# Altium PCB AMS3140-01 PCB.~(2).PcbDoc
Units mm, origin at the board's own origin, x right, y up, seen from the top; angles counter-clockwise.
Board outline 41 x 38 mm, 4 copper layers (Top Layer, Int1_T, Int2-B, Bottom (GND)), stack 1.57 mm thick; 5 components, 68 nets, 22 pads, 0 vias.
Unrouted connection lines stored in the file: 5.
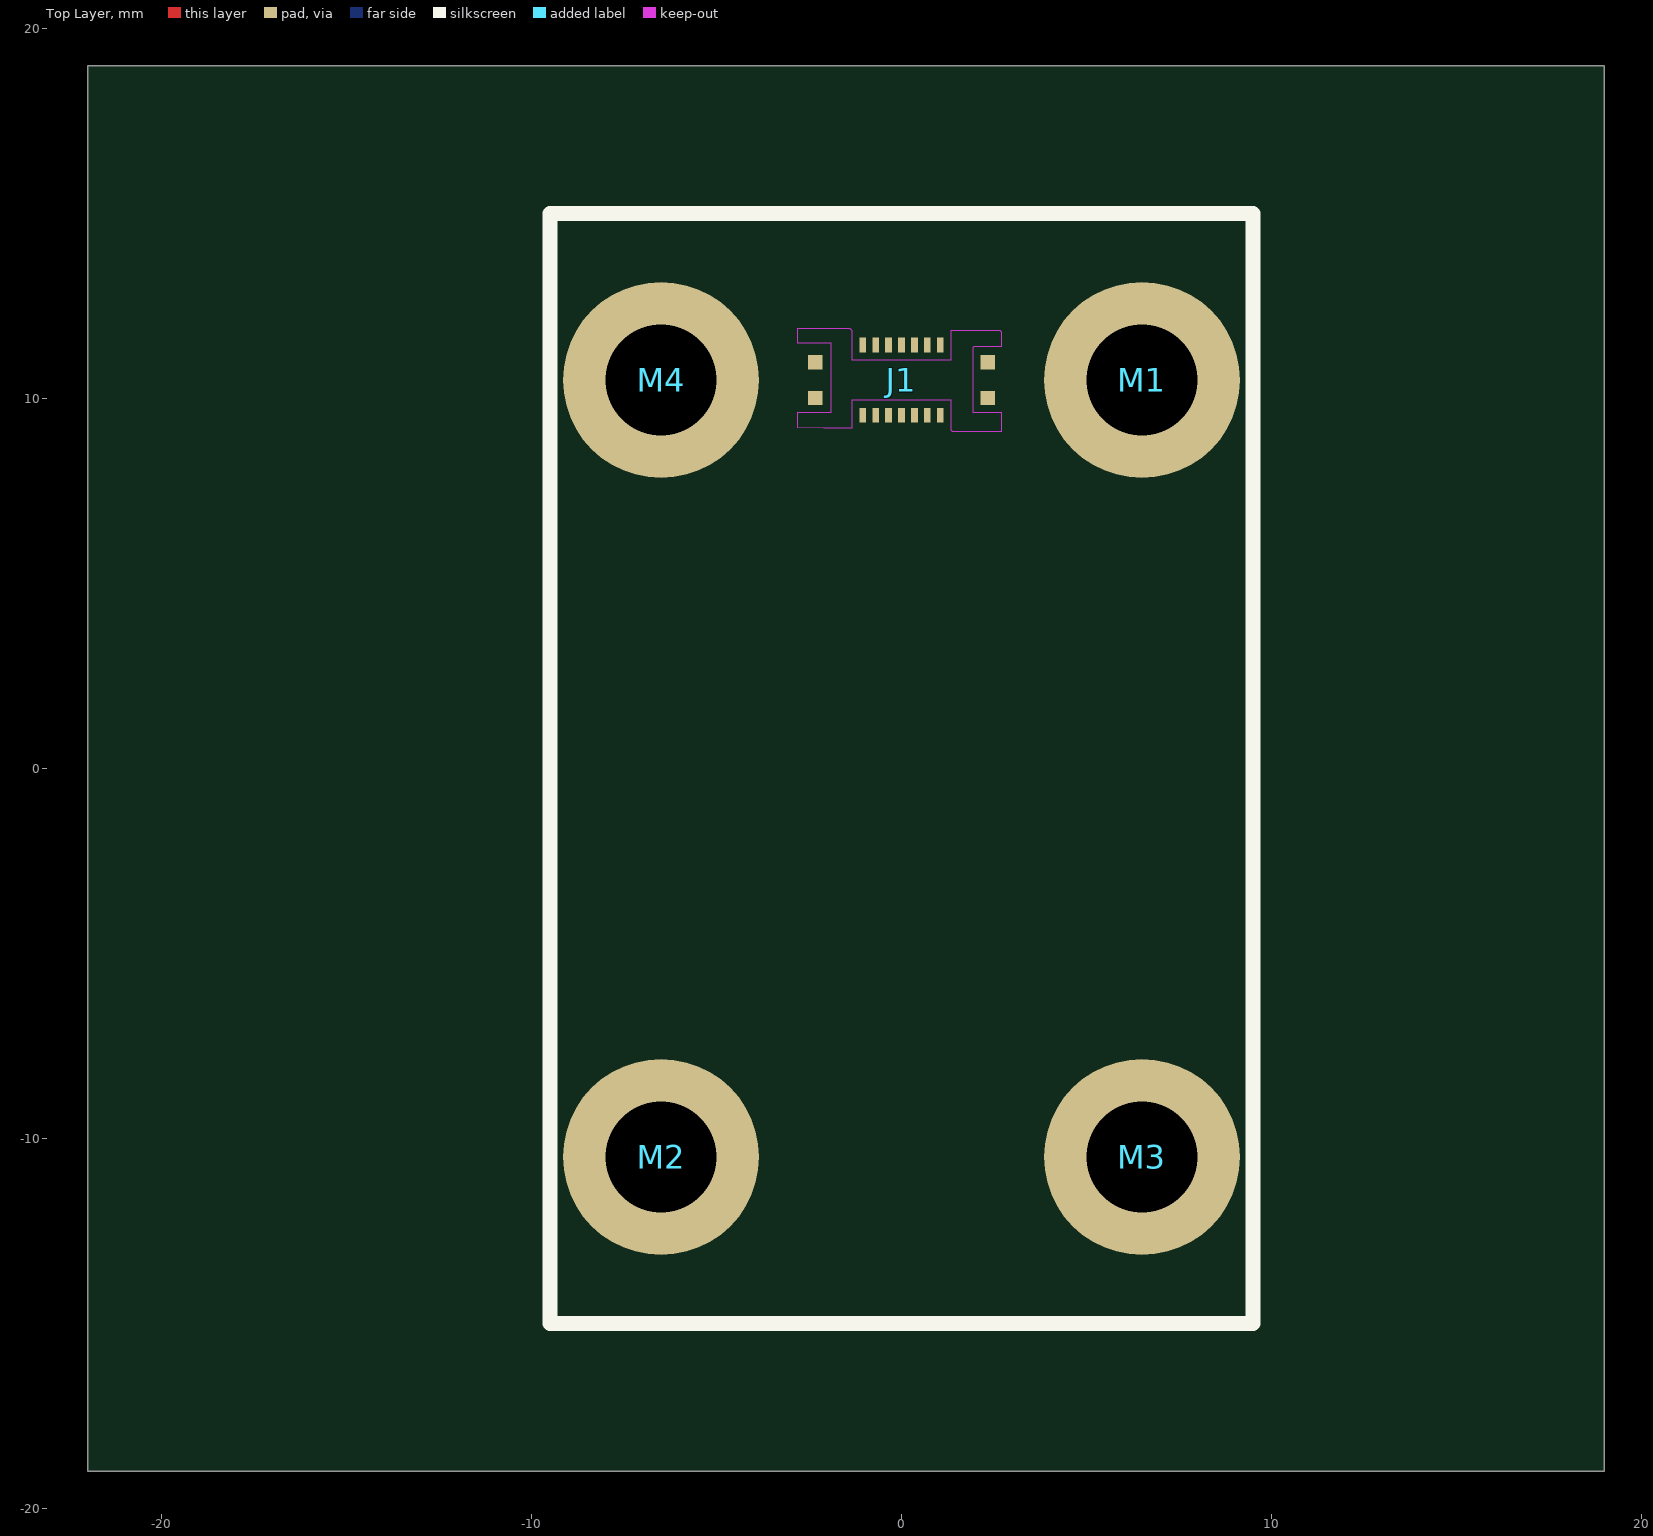
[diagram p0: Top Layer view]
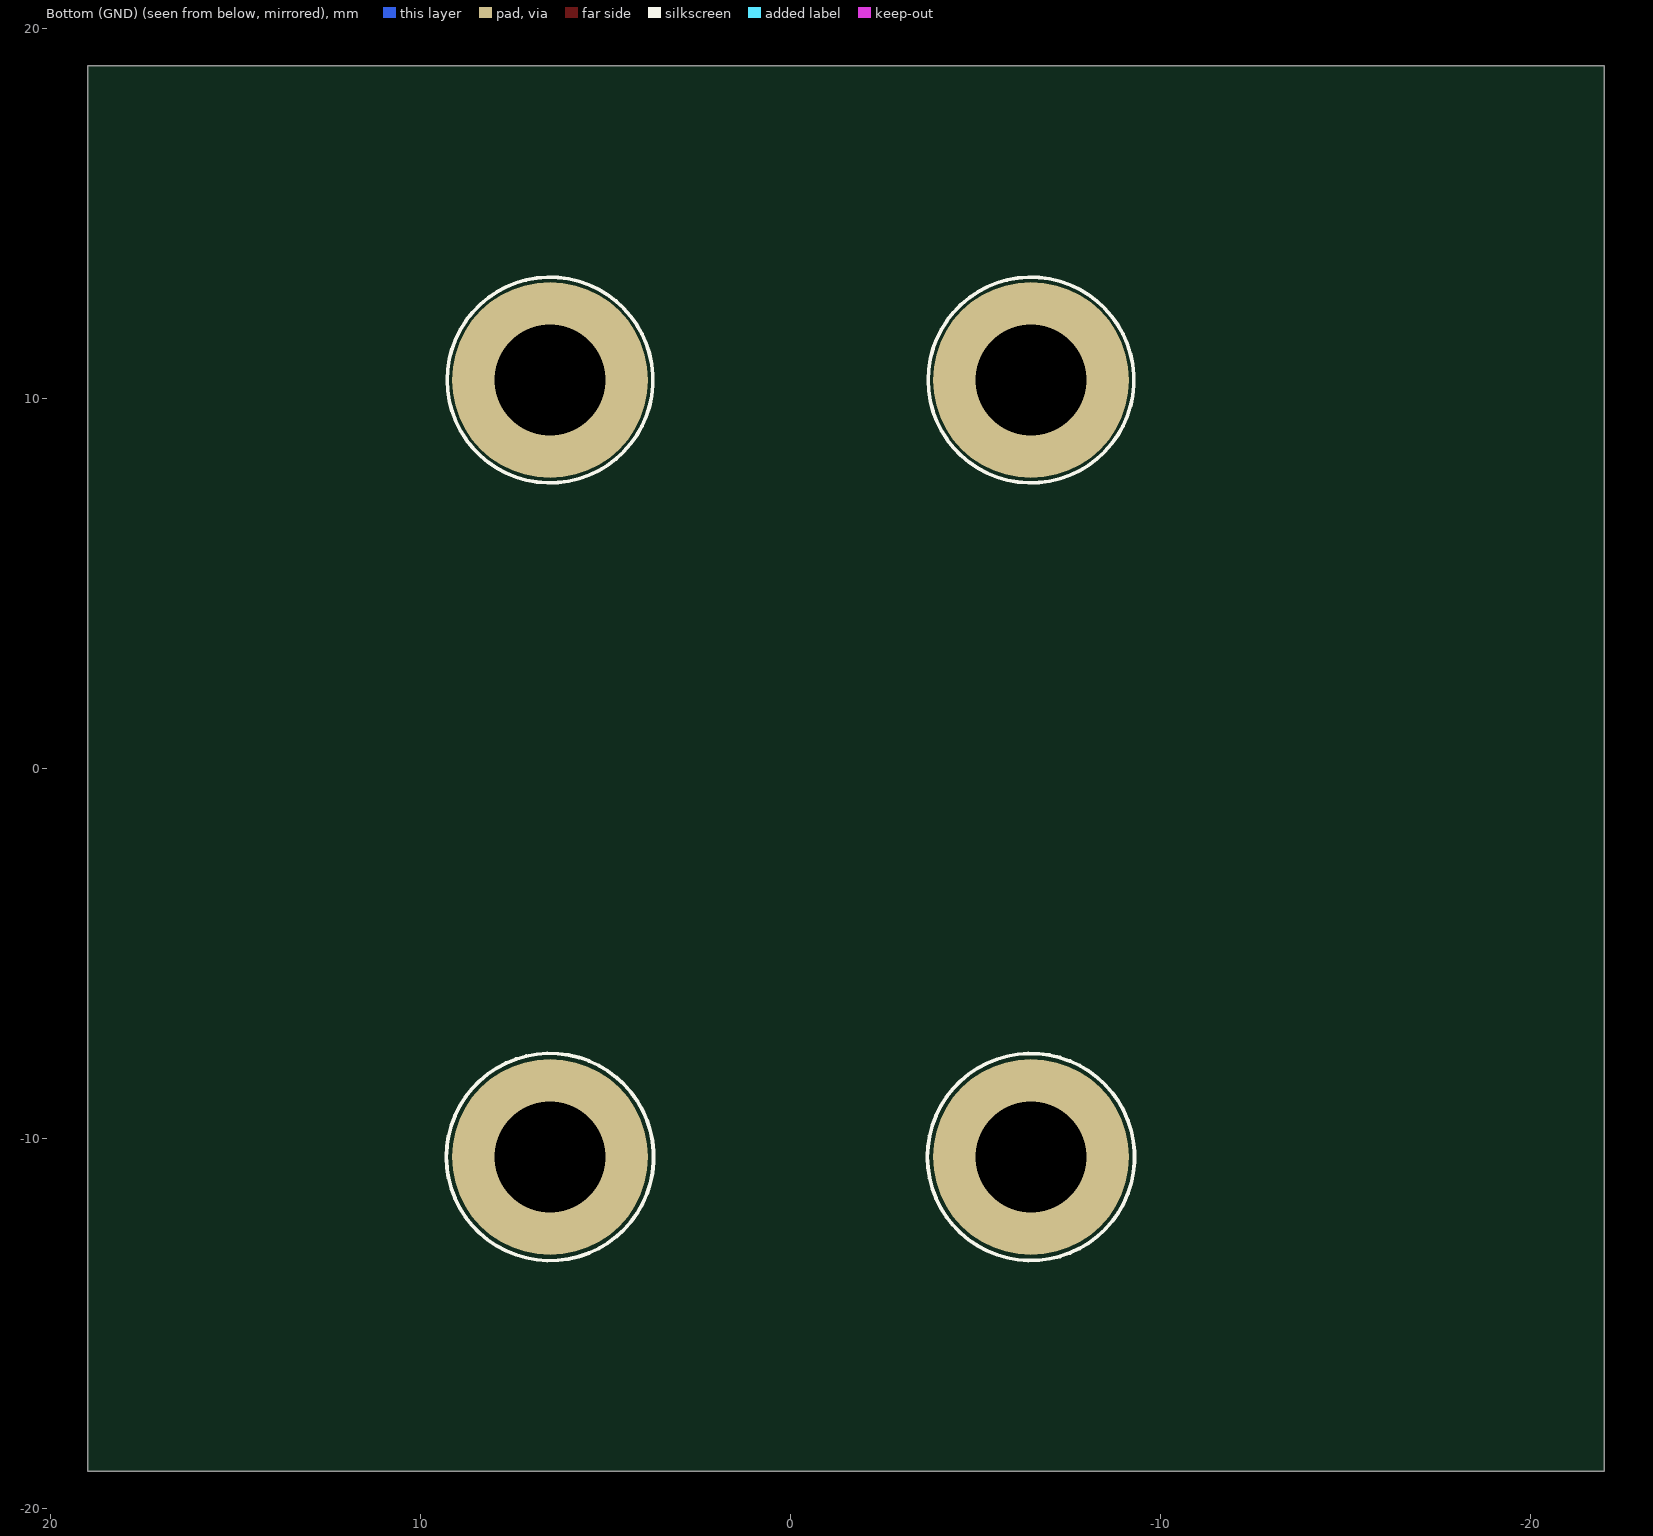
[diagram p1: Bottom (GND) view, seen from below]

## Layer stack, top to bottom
Top Solder: solder mask 0.025, SM-001, Dk 4
Top Layer: signal copper 0.035
Dielectric 1: core 0.36, Core-009, Dk 4.5
Int1_T: signal copper 0.035
Dielectric 6: prepreg 0.71, PP-006, Dk 4.1
Int2-B: signal copper 0.035
Dielectric 11: core 0.36, Core-009, Dk 4.5
Bottom (GND): signal copper 0.035
Bottom Solder: solder mask 0.025, SM-001, Dk 4

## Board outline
-22,-19 -22,19 19,19 19,-19

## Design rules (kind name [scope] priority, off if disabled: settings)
BoardOutlineClearance "BoardOutlineClearance inner layers" [(not IsKeepOut) and onMid] p1: gap=0.4 ignorepadtopadclearanceinfootprint=FALSE
BoardOutlineClearance "BoardOutlineClearance_1 outer layers" [(not IsKeepOut) and OnOutside] p2: gap=0.25 ignorepadtopadclearanceinfootprint=FALSE
Clearance Clearance_poly_50Ohm [InNetClass('50ohm')] p1: gap=0.3 ignorepadtopadclearanceinfootprint=FALSE except(0: Arc-Hole Track-Hole SMDPad-Hole THPad-Hole Via-Hole Fill-Hole Poly-Hole Region-Hole Text-Hole)
Clearance [not IsKeepOut vs not IsKeepOut] p2: gap=0.15 ignorepadtopadclearanceinfootprint=FALSE except(0: Arc-Hole Track-Hole SMDPad-Hole THPad-Hole Via-Hole Fill-Hole Poly-Hole Region-Hole Text-Hole; 0.2: Arc-Poly Track-Poly SMDPad-Poly THPad-Poly Via-Poly Fill-Poly Poly-Poly)
Clearance Clearance_keepout [All] p3: gap=0.001 ignorepadtopadclearanceinfootprint=FALSE except(0: Arc-Hole Track-Hole SMDPad-Hole THPad-Hole Via-Hole Fill-Hole Poly-Hole Region-Hole Text-Hole)
ComponentClearance [All] p1: gap=0.25 collisioncheckmode=3 verticalgap=0.2 showdistances=FALSE
DiffPairsRouting [All] p1: maxlimit=0.15 minlimit=0.15 mostfreqgap=0.15 toplayer_minwidth=0.15 toplayer_maxwidth=0.7 toplayer_prefwidth=0.15 midlayer1_minwidth=0.15 midlayer1_maxwidth=0.7 midlayer1_prefwidth=0.15 midlayer4_minwidth=0.15 midlayer4_maxwidth=0.7 midlayer4_prefwidth=0.15 bottomlayer_minwidth=0.15 bottomlayer_maxwidth=0.7 bottomlayer_prefwidth=0.15 maxuncoupledlength=12.5
Height [All] p1: minheight=0 maxheight=25 prefheight=12.5
HoleSize HoleSize-PTH [All] p1: absolutevalues=TRUE maxlimit=4 minlimit=0.25 maxpercent=80.000 minpercent=20.000
HoleToHoleClearance [All] p1: gap=0.35 allowstackedmicrovias=TRUE
MatchedLengths "Schematic Matched Net Lengths_1" [InNet('OUT_P')] p1: tolerance=2 checknetsindiffpair=TRUE checkdiffpairvsdiffpair=FALSE checkxsignals=FALSE checkothers=FALSE
MatchedLengths "Schematic Matched Net Lengths" [InNet('OUT_N')] p2: tolerance=2 checknetsindiffpair=TRUE checkdiffpairvsdiffpair=FALSE checkxsignals=FALSE checkothers=FALSE
MaxMinImpedance "Schematic Impedance Constraint_7" [InNet('OUTF_P')] p1: minimum=47,00 maximum=53,00
MaxMinImpedance "Schematic Impedance Constraint_6" [InNet('OUTF_N')] p2: minimum=47,00 maximum=53,00
MaxMinImpedance "Schematic Impedance Constraint_3" [InNet('NetR12_2')] p3: minimum=47,00 maximum=53,00
MaxMinImpedance "Schematic Impedance Constraint_2" [InNet('NetJ3_1')] p4: minimum=47,00 maximum=53,00
MinimumAnnularRing AR [All] p1: minimumring=0.174
MinimumSolderMaskSliver [All] p1: minsoldermaskwidth=0.08
PlaneClearance PlaneClearance-IPI [All] p1: clearance=0.25
PolygonConnect PolygonConnect-via [IsVia] p1: connectstyle=Direct reliefconductorwidth=0.254 reliefentries=4 polygonreliefangle="45 Angle" airgapwidth=0.254
PolygonConnect PolygonConnect-xTW_1_bottom [All vs OnLayer('Bottom Layer')] p2: connectstyle=Direct reliefconductorwidth=0.254 reliefentries=4 polygonreliefangle="90 Angle" airgapwidth=0.254
PolygonConnect PolygonConnect-xTW_1_bottom_1 [(PadIsPlated = 'False')] p3: connectstyle=Relief reliefconductorwidth=0.2 reliefentries=4 polygonreliefangle="90 Angle" airgapwidth=0.2
PolygonConnect PolygonConnect-big [AsMM(HoleDiameter) > 1] p4: connectstyle=Direct reliefconductorwidth=0.254 reliefentries=4 polygonreliefangle="90 Angle" airgapwidth=0.254
PolygonConnect PolygonConnect-xTW_1 [All] p5: connectstyle=Relief reliefconductorwidth=0.254 reliefentries=4 polygonreliefangle="90 Angle" airgapwidth=0.254
RoutingCorners [All] p1: cornerstyle=45-Degree minsetback=2.5 maxsetback=2.5
RoutingVias "RoutingVias > 0.45mm" [(ObjectKind = 'Via')] p1: holewidth=0.25 width=0.7 viastyle="Through Hole" minholewidth=0.25 minwidth=0.6 maxholewidth=0.9 maxwidth=1.25 // finishet hole size > 0.45mm
SilkToSilkClearance [All] p1: silktosilkclearance=0.2
SilkToSolderMaskClearance SilkscreenOverComponentPads [IsPad] p1: minsilkscreentomaskgap=0.04 clearancetoexposedcopper=TRUE
SolderMaskExpansion [All] p1: expansion=0 istentingtop=FALSE
Width Width-xTW [not IsKeepOut] p1: maxlimit=2 minlimit=0.15 preferedwidth=0.7
20 further rules are at their usual default settings.

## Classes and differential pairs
component class "247-722-03 Main": J1 M2 M3 M4
differential pair OUTF: +OUTF_P -OUTF_N
differential pair OUT: +OUT_P -OUT_N

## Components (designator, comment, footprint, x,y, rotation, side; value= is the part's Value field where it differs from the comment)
J1 "101R014FB110" 101R014FB110 0,10.5 r0 top locked (schematic designator J4)
M1 "9774010943R" TP_THT_1500_3000 6.5,10.5 r180 top locked
M2 "9774010943R" TP_THT_1500_3000 -6.5,-10.5 r180 top locked
M3 "9774010943R" TP_THT_1500_3000 6.5,-10.5 r180 top locked
M4 "9774010943R" TP_THT_1500_3000 -6.5,10.5 r180 top locked

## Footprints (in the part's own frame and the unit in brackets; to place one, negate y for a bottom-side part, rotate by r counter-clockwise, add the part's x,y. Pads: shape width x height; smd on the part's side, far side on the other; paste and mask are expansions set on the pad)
101R014FB110 [mm] "14pins + 2 power paths"
  rect 0.18x0.4 smd: 1(-1.05,-0.95) 2(-1.05,0.95) 3(-0.7,-0.95) 4(-0.7,0.95) 5(-0.35,-0.95) 6(-0.35,0.95) 7(0,-0.95) 8(0,0.95) 9(0.35,-0.95) 10(0.35,0.95) 11(0.7,-0.95) 12(0.7,0.95) 13(1.05,-0.95) 14(1.05,0.95)
  rect 0.4x0.385 smd: MP1(-2.33,-0.483) MP2(-2.33,0.483) MP3(2.33,-0.483) MP4(2.33,0.483)
  body extent -2.45,-0.99 2.45,1.01, height 0.78
TP_THT_1500_3000 [mm]
  round 5.3 / inner round 3.6 / far side round 5.3 hole 3: 1(0,0)
  body extent -2.17,-2.17 2.18,2.17, height 1.01

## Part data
J1: library part j_101R014FB110, "14pin + 2 power paths, 0.35mm pitch", Manufacturer="Amphenol ICC", Manufacturer_Name="Amphenol ICC / Aorora", Supplier Part Number 1=3577436
M1 M2 M3 M4: library part m_spacer_1mm_fi2.25_WA-SMST_9774010943, Manufacturer="Wurth Elektronik", Supplier Part Number 1=732-10938-1-ND

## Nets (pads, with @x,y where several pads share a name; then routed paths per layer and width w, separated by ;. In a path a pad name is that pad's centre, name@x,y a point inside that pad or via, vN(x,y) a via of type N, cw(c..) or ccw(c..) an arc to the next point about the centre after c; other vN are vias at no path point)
3V3: 
GND: J1.3 J1.9 J1.11 J1.13
NetC1_2: 
NetC2_1: 
NetC2_2: 
NetC3_2: 
NetC4_2: 
NetC5_2: 
NetC6_2: J1.1
NetC7_2: 
NetC13_2: 
NetC17_2: 
NetD1_2: 
NetD2_1: 
NetD2_2: 
NetD3_2: 
NetD4_1: 
NetD4_2: 
NetD5_1: 
NetD6_1: 
NetD6_2: 
NetF1_1: 
NetF3_2: 
NetIC1_5: 
NetIC1_8: 
NetIC1_12: 
NetIC1_15: 
NetJ3_1: 
NetJ5_1: 
NetM1_1: M1.1
NetM2_1: M2.1
NetM3_1: M3.1
NetM4_1: M4.1
NetR2_1: 
NetR4_1: 
NetR5_1: 
NetR6_1: 
NetR10_2: 
NetR11_2: 
NetR12_2: 
NetR14_2: 
NetR26_1: 
NetR27_1: 
NetR30_1: 
NetR31_2: 
NetR32_2: 
NetR33_2: 
NetR34_2: 
NetR35_2: 
NetR36_2: 
NetR37_2: 
NetR38_2: 
NetU2_6: 
OFFSET_N: J1.2
OFFSET_P: J1.6
OUT_N: J1.5
OUT_P: J1.7
OUTF_N: 
OUTF_P: 
PGND: J1.MP3 J1.MP4
TEMP_OK: J1.12
TEMP_OUT: J1.14
TEMP_REF: J1.10
V_amp: 
V_cooler: J1.MP1 J1.MP2
VCC: J1.8
VCC_F: 
Vin: 
pads on no net: J1.4

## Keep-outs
Top Layer:
  region: -1.9,11 -1.9,11.5 -2.769,11.5 -2.8,11.5 -2.8,11.9 -1.397,11.9 -1.34,11.843 -1.34,11.05 1.34,11.05 1.34,11.843 2.657,11.843 2.7,11.8 2.7,11.4 1.955,11.4 1.93,11.375 1.93,9.625 2.7,9.624 2.7,9.1 1.388,9.1 1.34,9.148 1.34,9.95 -1.34,9.95 -1.34,9.197 -2.097,9.197 -2.8,9.203 -2.8,9.624 -1.9,9.625 -1.9,10.9

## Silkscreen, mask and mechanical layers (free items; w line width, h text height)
Top Overlay:
  lines w0.4: -9.5,-15 -9.5,15 9.5,15 9.5,-15 -9.5,-15
Bottom Overlay:
  circle w0.1: c-6.5,-10.5 r2.8
  circle w0.1: c6.5,-10.5 r2.802
  circle w0.1: c6.5,10.5 r2.78
  circle w0.1: c-6.5,10.5 r2.78
  pour cut-out: 3.72,10.5 ccw(c6.5,10.5) 6.5,7.72 ccw(c6.5,10.5) 9.28,10.5 ccw(c6.5,10.5) 6.5,13.28 ccw(c6.5,10.5)
  pour cut-out: -9.28,10.5 ccw(c-6.5,10.5) -6.5,7.72 ccw(c-6.5,10.5) -3.72,10.5 ccw(c-6.5,10.5) -6.5,13.28 ccw(c-6.5,10.5)
  pour cut-out: 3.698,-10.5 ccw(c6.5,-10.5) 6.5,-13.302 ccw(c6.5,-10.5) 9.302,-10.5 ccw(c6.5,-10.5) 6.5,-7.698 ccw(c6.5,-10.5)
  pour cut-out: -9.3,-10.5 ccw(c-6.5,-10.5) -6.5,-13.3 ccw(c-6.5,-10.5) -3.7,-10.5 ccw(c-6.5,-10.5) -6.5,-7.7 ccw(c-6.5,-10.5)
Mechanical 1:
  lines w0.1: -71.8,-19 72,-19 72,45 -71.8,45 -71.8,-19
